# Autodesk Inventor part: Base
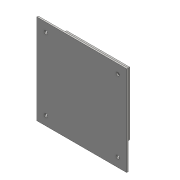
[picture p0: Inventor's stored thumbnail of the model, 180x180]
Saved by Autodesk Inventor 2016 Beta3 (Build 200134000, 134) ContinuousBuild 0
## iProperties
Created: 2016-03
Part Number: Base
Material: Generic
Document SubType Name: Modeling
Designer: Gaurav
Density: 1 g/cm^3
Appearance: Default
Author: Gaurav
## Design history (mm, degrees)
sketch "Sketch1"
  geometry: L1 (150, 150)-(-150, 150); L2 (-150, 150)-(-150, -150); L3 (-150, -150)-(150, -150); L4 (150, -150)-(150, 150); L5 (150, 150)-(-150, -150); L6 (-150, 150)-(150, -150); 1 further point
  constraints: 12 end point, 2 midpoint, 2 parallel, 1 horizontal, 1 perpendicular
  dimensions: "d0" = 300 distance of L3.end L2.end; "d1" = 300 distance of L2.end L1.end
extrude "Extrusion1" new body sketch "Sketch1" distance "d2" = 5; taper "d3" = 0 deg
sketch "Sketch2"
  geometry: L1 (-120, 0)-(92.63, 0); L2 (0, -120)-(0, 155.14); C1 r 5.5 at (-120, -120); C2 r 5.5 at (120, -120); C3 r 5.5 at (-120, 120); C4 r 5.5 at (120, 120); 1 further point
  constraints: 4 centre point, 4 end point, 3 symmetric about line, 1 horizontal, 1 vertical, 3 other
  dimensions: "d4" = 11 diameter of C1
extrude "Extrusion2" cut sketch "Sketch2" distance "d5" = 5; taper "d6" = 0 deg
sketch "Sketch3"
  geometry: L1 (-105, -105)-(105, -105); L2 (105, -105)-(105, 105); L3 (105, 105)-(-105, 105); L4 (-105, 105)-(-105, -105); L5 (-105, -105)-(105, 105); L6 (105, -105)-(-105, 105); L7 (-100, -100)-(100, -100); L8 (100, -100)-(100, 100); L9 (100, 100)-(-100, 100); L10 (-100, 100)-(-100, -100); 1 further point
  constraints: 20 end point, 4 parallel, 2 midpoint, 2 perpendicular, 1 horizontal, 3 other
  dimensions: "d7" = 210 distance of L3.end L2.end; "d8" = 210 distance of L2.end L1.end; "d9" = 5 distance between parallel lines of L4 L10
extrude "Extrusion3" join sketch "Sketch3" distance "d10" = 50; taper "d11" = 0 deg
body "Solid1"
